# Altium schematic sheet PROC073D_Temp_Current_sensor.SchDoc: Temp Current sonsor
size 431 x 279 mm; Date: Not shown in title block; ApprovedBy: Not shown in title block; CheckedBy: Not shown in title block; Author: Not shown in title block; CompanyName: Not shown in title block; DrawnBy: Charles F. Oladimeji; Engineer: Not shown in title block; Organization: Not shown in title block; Address1: Not shown in title block; Address2: Not shown in title block; Address3: Not shown in title block; Address4: Not shown in title block; DocumentNumber: 8; Revision: Use project parameter SCH_Rev; SheetNumber: 8; SheetTotal: 13; PageSetup: Record=PageOptions¦CenterHorizontal=True¦CenterVertical=True¦PrintScale=1.00¦XCorrection=1.00¦YCorrection=1.00¦PrintKind=0¦BorderSize=5000000¦LeftOffset=0¦BottomOffset=0¦Orientation=2¦PaperLength=1000¦PaperWidth=1000¦Scale=100¦PaperSource=15¦PrintQuality=600¦MediaType=1¦DitherType=10¦PaperKind=Letter¦PrintScaleMode=1
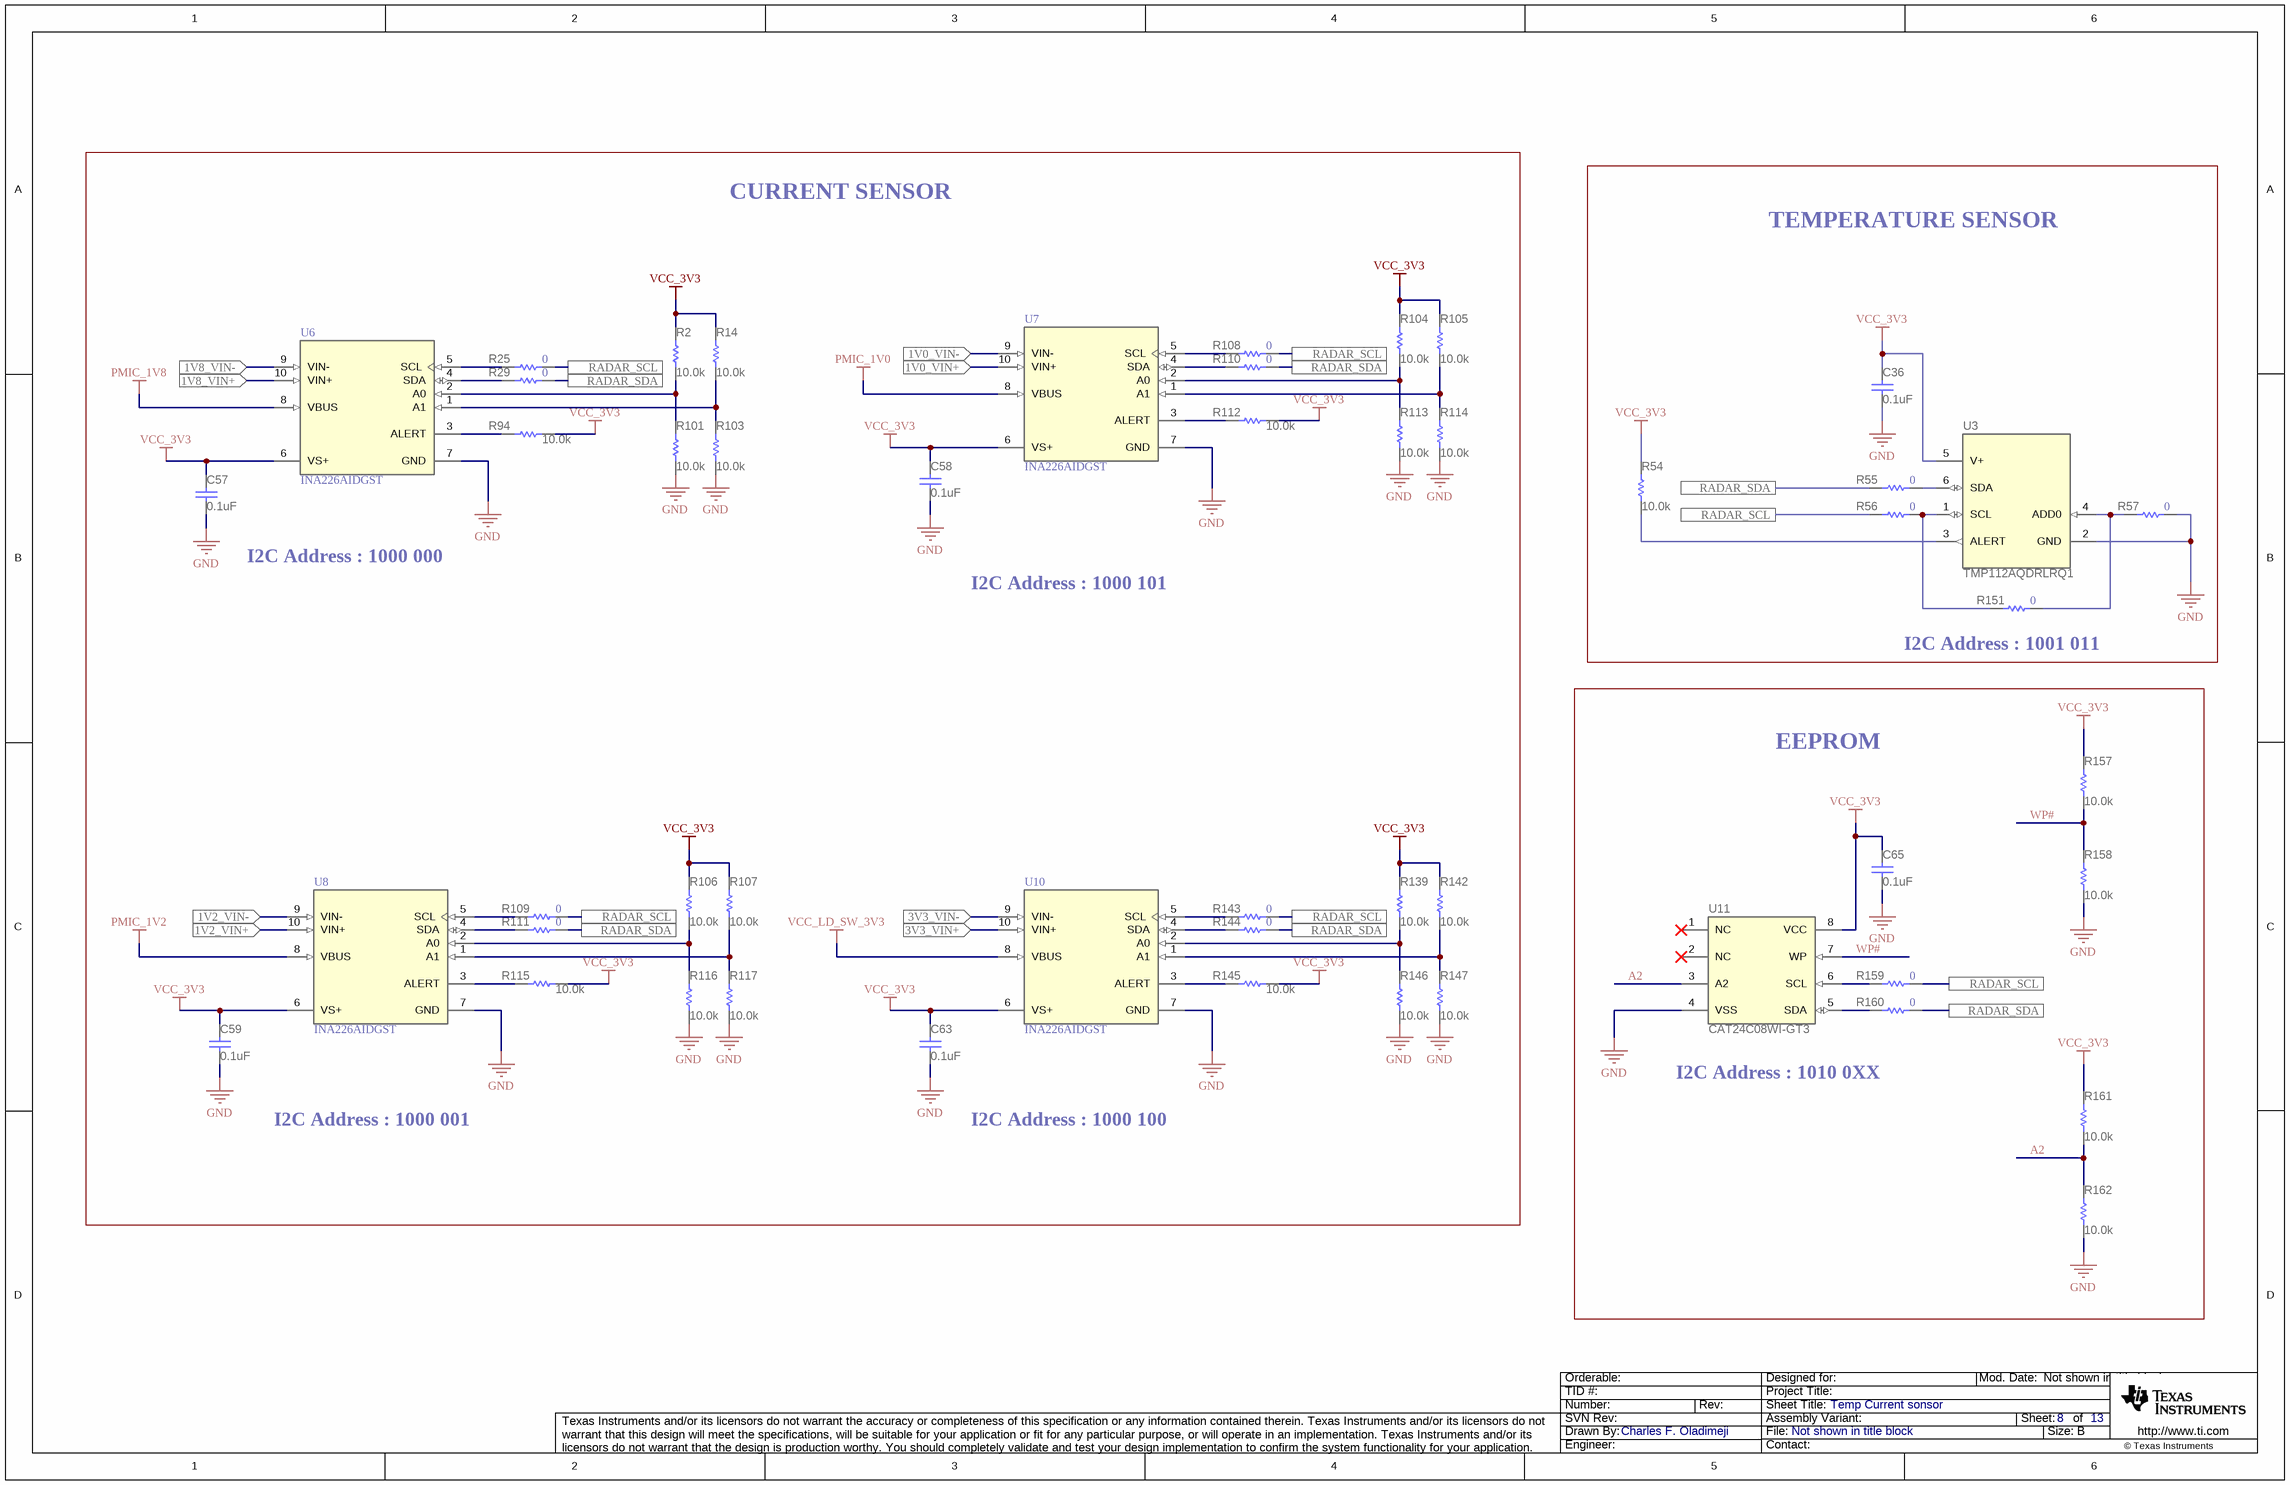
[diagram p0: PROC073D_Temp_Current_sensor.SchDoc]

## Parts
C36  ValueDisplayed: 0.1uF  [0402L]  (hidden comment: CGA2B3X7R1H104K050BB)
C57  ValueDisplayed: 0.1uF  [0402L]  (hidden comment: CGA2B3X7R1H104K050BB)
C58  ValueDisplayed: 0.1uF  [0402L]  (hidden comment: CGA2B3X7R1H104K050BB)
C59  ValueDisplayed: 0.1uF  [0402L]  (hidden comment: CGA2B3X7R1H104K050BB)
C63  ValueDisplayed: 0.1uF  [0402L]  (hidden comment: CGA2B3X7R1H104K050BB)
C65  ValueDisplayed: 0.1uF  [0402L]  (hidden comment: CGA2B3X7R1H104K050BB)
R2  ValueDisplayed: 10.0k  [0402L]  (hidden comment: CRCW040210K0FKED)
R14  ValueDisplayed: 10.0k  [0402L]  (hidden comment: CRCW040210K0FKED)
R25  ValueDisplayed: 0  [0201]  (hidden comment: CRCW02010000Z0ED)
R29  ValueDisplayed: 0  [0201]  (hidden comment: CRCW02010000Z0ED)
R54  ValueDisplayed: 10.0k  [0402L]  (hidden comment: CRCW040210K0FKED)
R55  ValueDisplayed: 0  [0201]  (hidden comment: CRCW02010000Z0ED)
R56  ValueDisplayed: 0  [0201]  (hidden comment: CRCW02010000Z0ED)
R57  Res_ohm: 0  [0402]  (hidden comment: CRCW04020000Z0ED)
R94  ValueDisplayed: 10.0k  [0402L]  (hidden comment: CRCW040210K0FKED)
R101  ValueDisplayed: 10.0k  [0402L]  (hidden comment: CRCW040210K0FKED)
R103  ValueDisplayed: 10.0k  [0402L]  (hidden comment: CRCW040210K0FKED)
R104  ValueDisplayed: 10.0k  [0402L]  (hidden comment: CRCW040210K0FKED)
R105  ValueDisplayed: 10.0k  [0402L]  (hidden comment: CRCW040210K0FKED)
R106  ValueDisplayed: 10.0k  [0402L]  (hidden comment: CRCW040210K0FKED)
R107  ValueDisplayed: 10.0k  [0402L]  (hidden comment: CRCW040210K0FKED)
R108  ValueDisplayed: 0  [0201]  (hidden comment: CRCW02010000Z0ED)
R109  ValueDisplayed: 0  [0201]  (hidden comment: CRCW02010000Z0ED)
R110  ValueDisplayed: 0  [0201]  (hidden comment: CRCW02010000Z0ED)
R111  ValueDisplayed: 0  [0201]  (hidden comment: CRCW02010000Z0ED)
R112  ValueDisplayed: 10.0k  [0402L]  (hidden comment: CRCW040210K0FKED)
R113  ValueDisplayed: 10.0k  [0402L]  (hidden comment: CRCW040210K0FKED)
R114  ValueDisplayed: 10.0k  [0402L]  (hidden comment: CRCW040210K0FKED)
R115  ValueDisplayed: 10.0k  [0402L]  (hidden comment: CRCW040210K0FKED)
R116  ValueDisplayed: 10.0k  [0402L]  (hidden comment: CRCW040210K0FKED)
R117  ValueDisplayed: 10.0k  [0402L]  (hidden comment: CRCW040210K0FKED)
R139  ValueDisplayed: 10.0k  [0402L]  (hidden comment: CRCW040210K0FKED)
R142  ValueDisplayed: 10.0k  [0402L]  (hidden comment: CRCW040210K0FKED)
R143  ValueDisplayed: 0  [0201]  (hidden comment: CRCW02010000Z0ED)
R144  ValueDisplayed: 0  [0201]  (hidden comment: CRCW02010000Z0ED)
R145  ValueDisplayed: 10.0k  [0402L]  (hidden comment: CRCW040210K0FKED)
R146  ValueDisplayed: 10.0k  [0402L]  (hidden comment: CRCW040210K0FKED)
R147  ValueDisplayed: 10.0k  [0402L]  (hidden comment: CRCW040210K0FKED)
R151  Res_ohm: 0  [0402]  (hidden comment: CRCW04020000Z0ED)
R157  ValueDisplayed: 10.0k  [0402L]  (hidden comment: CRCW040210K0FKED)
R158  ValueDisplayed: 10.0k  [0402L]  (hidden comment: CRCW040210K0FKED)
R159  ValueDisplayed: 0  [0201]  (hidden comment: CRCW02010000Z0ED)
R160  ValueDisplayed: 0  [0201]  (hidden comment: CRCW02010000Z0ED)
R161  ValueDisplayed: 10.0k  [0402L]  (hidden comment: CRCW040210K0FKED)
R162  ValueDisplayed: 10.0k  [0402L]  (hidden comment: CRCW040210K0FKED)
U3  TMP112AQDRLRQ1  [DRL0006A]
U6  INA226AIDGST  [DGS0010A_L]
U7  INA226AIDGST  [DGS0010A_L]
U8  INA226AIDGST  [DGS0010A_L]
U10  INA226AIDGST  [DGS0010A_L]
U11  CAT24C08WI-GT3  [SOIC-8]

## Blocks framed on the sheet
CURRENT SENSOR: C57-C59 C63 R2 R14 R25 R29 R94 R101 R103-R117 R139 R142-R147 U6-U8 U10
TEMPERATURE SENSOR: C36 R54-R57 R151 U3
EEPROM: C65 R157-R162 U11

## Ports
1V0_VIN+ (in), 1V0_VIN- (in), 1V2_VIN+ (in), 1V2_VIN- (in), 1V8_VIN+ (in), 1V8_VIN- (in), 3V3_VIN+ (in), 3V3_VIN- (in), RADAR_SCL, RADAR_SDA

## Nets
GND: C36.1 C57.1 C58.1 C59.1 C63.1 C65.1 R57.2 R101.1 R103.1 R113.1 R114.1 R116.1 R117.1 R146.1 R147.1 R158.1 R162.1 U3.2(GND) U6.7(GND) U7.7(GND) U8.7(GND) U10.7(GND) U11.4(VSS)
PMIC_1V0: U7.8(VBUS)
PMIC_1V2: U8.8(VBUS)
PMIC_1V8: U6.8(VBUS)
VCC_3V3: C36.2 C57.2 C58.2 C59.2 C63.2 C65.2 R2.2 R14.2 R54.2 R94.1 R104.2 R105.2 R106.2 R107.2 R112.1 R115.1 R139.2 R142.2 R145.1 R157.2 R161.2 U3.5(V+) U6.6(VS+) U7.6(VS+) U8.6(VS+) U10.6(VS+) U11.8(VCC)
VCC_LD_SW_3V3: U10.8(VBUS)
1V0_VIN+: U7.10(VIN+) ; port 1V0_VIN+
1V0_VIN-: U7.9(VIN-) ; port 1V0_VIN-
1V2_VIN+: U8.10(VIN+) ; port 1V2_VIN+
1V2_VIN-: U8.9(VIN-) ; port 1V2_VIN-
1V8_VIN+: U6.10(VIN+) ; port 1V8_VIN+
1V8_VIN-: U6.9(VIN-) ; port 1V8_VIN-
3V3_VIN+: U10.10(VIN+) ; port 3V3_VIN+
3V3_VIN-: U10.9(VIN-) ; port 3V3_VIN-
A2: R161.1 R162.2 U11.3(A2)
RADAR_SCL: R25.2 R56.1 R108.2 R109.2 R143.2 R159.2 ; port RADAR_SCL
RADAR_SDA: R29.2 R55.1 R110.2 R111.2 R144.2 R160.2 ; port RADAR_SDA
WP#: R157.1 R158.2 U11.7(WP)
NetR2_1: R2.1 R101.2 U6.2(A0)
NetR14_1: R14.1 R103.2 U6.1(A1)
NetR25_1: R25.1 U6.5(SCL)
NetR29_1: R29.1 U6.4(SDA)
NetR54_1: R54.1 U3.3(ALERT)
NetR55_2: R55.2 U3.6(SDA)
NetR56_2: R56.2 R151.1 U3.1(SCL)
NetR57_1: R57.1 R151.2 U3.4(ADD0)
NetR94_2: R94.2 U6.3(ALERT)
NetR104_1: R104.1 R113.2 U7.2(A0)
NetR105_1: R105.1 R114.2 U7.1(A1)
NetR106_1: R106.1 R116.2 U8.2(A0)
NetR107_1: R107.1 R117.2 U8.1(A1)
NetR108_1: R108.1 U7.5(SCL)
NetR109_1: R109.1 U8.5(SCL)
NetR110_1: R110.1 U7.4(SDA)
NetR111_1: R111.1 U8.4(SDA)
NetR112_2: R112.2 U7.3(ALERT)
NetR115_2: R115.2 U8.3(ALERT)
NetR139_1: R139.1 R146.2 U10.2(A0)
NetR142_1: R142.1 R147.2 U10.1(A1)
NetR143_1: R143.1 U10.5(SCL)
NetR144_1: R144.1 U10.4(SDA)
NetR145_2: R145.2 U10.3(ALERT)
NetR159_1: R159.1 U11.6(SCL)
NetR160_1: R160.1 U11.5(SDA)

Not connected (* = marked no-connect by the designer): U11 1(NC)* 2(NC)*

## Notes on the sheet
- I2C Address : 1000 000
- I2C Address : 1000 101
- (near R151) I2C Address : 1001 011
- I2C Address : 1010 0XX
- I2C Address : 1000 001
- I2C Address : 1000 100

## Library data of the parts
C36 C57-C59 C63 C65 = CMP-0006325-2: CAP, CERM, 0.1 uF, 50 V, +/- 10%, X7R, AEC-Q200 Grade 1, 0402; Manufacturer: TDK; TaMin_C: -55°C; ESR_ohm: 0.039064; Polarized: N; SizeAreaWB_mm2: 3; Value1: 0.039064 ohm; U/M: EA; Value: 0.1uF; TaMax_C: 125°C; SizeZ_mm: 0.6; SizeX_mm: 1; SizeY_mm: 0.5; Cap_Case: 0402; Value2: 50V; AEC Qualified: Y; Cap_F: 100nF; IRMS_A: 8.14669dA; AEC Category: Q200
R2 R14 R54 R94 R101 R103-R107 R112-R117 R139 R142 R145-R147 R157 R158 R161 R162 = CMP-0025958-3: RES, 10.0 k, 1%, 0.063 W, AEC-Q200 Grade 0, 0402; Manufacturer: Vishay-Dale; Power_W: 63mW; TempCo: 100 ppm/C; Value_Code: 10k0; Value: 10.0k; EIA_Code: E96; Res_ohm: 10k; SizeX_mm: 1; SizeY_mm: 0.5; SizeZ_mm: 0.6; Value2: 0.063W; AEC Qualified: Y; VDC_V: 50V; AEC Category: Q200; AEC Grade: 0
R25 R29 R55 R56 R108-R111 R143 R144 R159 R160 = CMP-0027008-4: RES, 0, 5%, 0.05 W, 0201; Manufacturer: Vishay-Dale; Power_W: 50mW; TempCo: ppm/C; Value_Code: 0000; Value: 0; EIA_Code: E24; SizeX_mm: 0.6; SizeY_mm: 0.3; SizeZ_mm: 0.26; Value2: 0.05W; SizeArea_mm2: 0.18; AEC Qualified: N; AEC Category: Q200
R57 = CMP-0026822-3: RES, 0, 5%, 0.063 W, AEC-Q200 Grade 0, 0402; Manufacturer: Vishay-Dale; Power_W: 63mW; TempCo: 200 ppm/C; Value_Code: 0000; Value: 0; EIA_Code: E24; SizeX_mm: 1; SizeY_mm: 0.5; SizeZ_mm: 0.6; Value2: 0.063W; CompType: Resistor; AEC Qualified: Y; VDC_V: 50V; AEC Category: Q200; INSTALLATION: DNP
R151 = CMP-0026822-3: RES, 0, 5%, 0.063 W, AEC-Q200 Grade 0, 0402; Manufacturer: Vishay-Dale; Power_W: 63mW; TempCo: 200 ppm/C; Value_Code: 0000; Value: 0; EIA_Code: E24; SizeX_mm: 1; SizeY_mm: 0.5; SizeZ_mm: 0.6; Value2: 0.063W; CompType: Resistor; AEC Qualified: Y; VDC_V: 50V; AEC Category: Q200
U3 = CMP-0067398-2: Automotive Grade, 1.4V-Capable +/-0.5degC Temperature Sensor with Alert Function and I2C/SMBus, DRL0006A (SOT-OTHER-6); Manufacturer: Texas Instruments; SizeZ_mm: 0.6; SizeX_mm: 1.6; SizeArea_mm2: 2.56; CompType: IC; U/M: EA; SizeAreaWB_mm2: 6.76
U6-U8 U10 = CMP-0037978-1: High-Side Measurement, Bi-Directional Current / Power Monitor with I2C Interface, 2.7 to 5.5 V, -40 to 125 degC, 10-pin SOP (DGS10), Green (RoHS & no Sb/Br); Vs(Min)(V): 2.7; Rating: Catalog; Quiescent Current (+/-)(Typ)(mA): 0.33; Input Offset (+/-)(Max)(uV): 10; CMRR(Min)(dB): 126; Vs(Max)(V): 5.5; Common Mode Range(Max)(V): 36; Input Offset Drift (+/-)(Max)(uV/Degrees Celsius): 0.1; Common Mode Range(Min)(V): 0; SubFamily: Current Shunt Monitor; Gain(V/V): 1; Small-Signal Bandwidth(Typ)(MHz): 0.007
U11 = CMP-0005309-2: IC, EEPROM, 8KBIT, 400KHZ, 8SOIC; Manufacturer: ON Semiconductor; SizeAreaWB_mm2: 55.131; SizeZ_mm: 1.75; SizeX_mm: 5.99; SizeY_mm: 4.9; SizeArea_mm2: 29.351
